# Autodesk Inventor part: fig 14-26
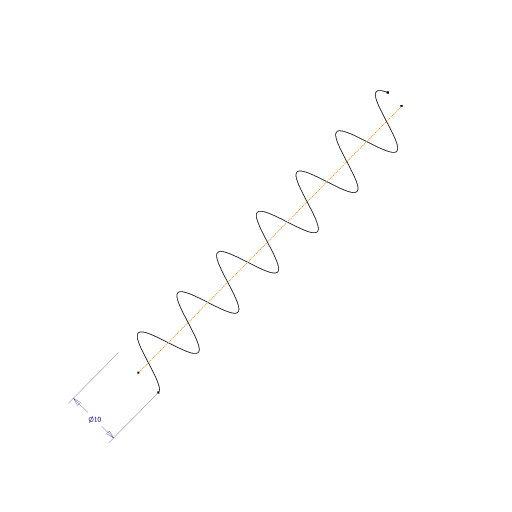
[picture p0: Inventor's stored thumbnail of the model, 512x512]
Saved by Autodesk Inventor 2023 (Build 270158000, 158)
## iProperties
Created: 2007-03
Part Number: fig 14-26
Document SubType Name: Modeling
Designer: Administrator
Density: 1 g/cm^3
Material: Generic
Appearance: Default
Author: Administrator
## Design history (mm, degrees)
node "Sketch1"
sketch "3D Sketch1"
  node "Helical Curve2" dims "d4" = 10, "d5" = 66.31, "d6" = 10, "d7" = 0
